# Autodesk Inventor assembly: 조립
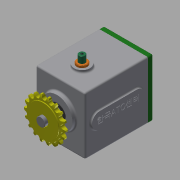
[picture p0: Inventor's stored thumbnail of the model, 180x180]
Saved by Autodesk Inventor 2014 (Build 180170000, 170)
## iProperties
Created: 2018-12
Part Number: 조립
Document SubType Name: Assembly
Designer: kh
Mass: 2985.14 g
Surface Area: 1968.34 cm^2
Volume: 815.226 cm^3
Density: 3.66174 g/cm^3
Author: kh
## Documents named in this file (16)
- C:\Users\kh\Desktop\381207V1019\조립.iam
- C:\Users\kh\Desktop\381207V1019\멈춤나사 M3x8.ipt
- C:\Users\kh\Desktop\381207V1019\메인 기어 축.ipt
- C:\Users\kh\Desktop\381207V1019\베어링 608.ipt
- C:\Users\kh\Desktop\381207V1019\베어링 6003.ipt
- C:\Users\kh\Desktop\381207V1019\볼트 M4 x 10.ipt
- C:\Users\kh\Desktop\381207V1019\부시.ipt
- C:\Users\kh\Desktop\381207V1019\서브 기어 축.ipt
- C:\Users\kh\Desktop\381207V1019\스프로킷.ipt
- C:\Users\kh\Desktop\381207V1019\슬라이더.ipt
- C:\Users\kh\Desktop\381207V1019\오일 실 8 22 7.ipt
- C:\Users\kh\Desktop\381207V1019\오일 실 17 32 8.ipt
- C:\Users\kh\Desktop\381207V1019\커버.ipt
- C:\Users\kh\Desktop\381207V1019\키 5 x 5 x 18.ipt
- C:\Users\kh\Desktop\381207V1019\본체.ipt
- C:\Users\kh\Desktop\381207V1019\가변스프링.ipt
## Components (1 placed, 1 different names)
1. 가변스프링:1
